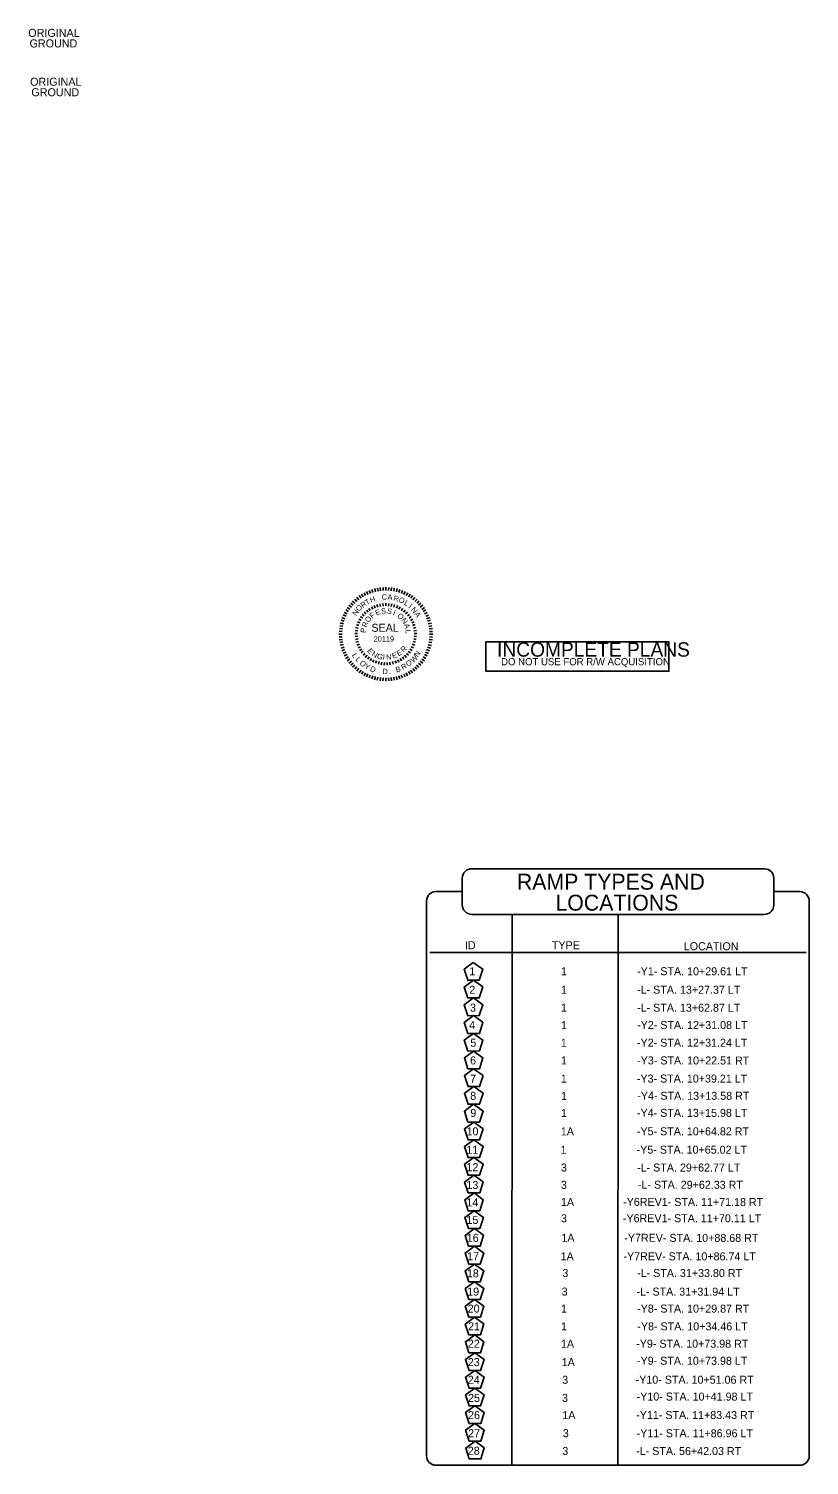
# Model space of a CAD drawing. Extents: x 1725232 to 1728895, y 538685 to 540544.
# Drawn here: x 1728215 to 1728895, y 539219 to 540472 of the extents above; entities that cross this region are included whole.
import ezdxf

# ---------------------------------------------------------------- set-up
doc = ezdxf.new("R2010")
doc.units = 0
for name, color, linetype in [('Default', 7, 'Continuous'), ('DEV BORDER CELL', 7, 'Continuous'), ('Gray Area Fill Shapes', 7, 'Continuous'), ('Prop Dimension Text', 7, 'Continuous'), ('Sheet Sticker Incomplete CELL', 7, 'Continuous'), ('Sheet Title CELL', 7, 'Continuous')]:
    doc.layers.add(name, color=color, linetype=linetype)

msp = doc.modelspace()

# ---------------------------------------------------------------- linework, layer by layer
at = {"layer": 'Default'}
for p, q in [((1728636.1, 539699.3), (1728636, 539218.9)), ((1728728.5, 539699.3), (1728728.4, 539218.9)), ((1728564.4, 539666.2), (1728728.5, 539666.2)), ((1728728.5, 539666.2), (1728892.6, 539666.1))]:
    msp.add_line(p, q, dxfattribs=at)
for points in [[(1728602.3, 539657.4), (1728594.2, 539651.5), (1728597.4, 539642), (1728607.4, 539642), (1728610.5, 539651.6)], [(1728602.4, 539642), (1728594.3, 539636), (1728597.4, 539626.5), (1728607.5, 539626.5), (1728610.5, 539636.1)], [(1728602.4, 539626.5), (1728594.3, 539620.6), (1728597.5, 539611), (1728607.5, 539611.1), (1728610.6, 539620.6)], [(1728602.5, 539611.1), (1728594.4, 539605.1), (1728597.5, 539595.6), (1728607.6, 539595.6), (1728610.6, 539605.2)], [(1728602.5, 539595.6), (1728594.4, 539589.7), (1728597.6, 539580.1), (1728607.6, 539580.2), (1728610.7, 539589.7)], [(1728602.6, 539580.1), (1728594.5, 539574.2), (1728597.6, 539564.7), (1728607.7, 539564.7), (1728610.7, 539574.3)], [(1728602.6, 539564.7), (1728594.5, 539558.8), (1728597.7, 539549.2), (1728607.7, 539549.2), (1728610.8, 539558.8)], [(1728602.7, 539549.2), (1728594.6, 539543.3), (1728597.7, 539533.8), (1728607.8, 539533.8), (1728610.8, 539543.4)], [(1728602.6, 539533.7), (1728594.5, 539527.7), (1728597.6, 539518.2), (1728607.7, 539518.2), (1728610.8, 539527.8)], [(1728602.7, 539518.2), (1728594.6, 539512.3), (1728597.7, 539502.7), (1728607.7, 539502.8), (1728610.8, 539512.3)], [(1728602.7, 539502.8), (1728594.6, 539496.8), (1728597.7, 539487.3), (1728607.8, 539487.3), (1728610.9, 539496.9)], [(1728602.8, 539487.3), (1728594.7, 539481.4), (1728597.8, 539471.8), (1728607.8, 539471.9), (1728610.9, 539481.4)], [(1728602.8, 539471.8), (1728594.7, 539465.9), (1728597.9, 539456.4), (1728607.9, 539456.4), (1728611, 539466)], [(1728602.9, 539456.4), (1728594.8, 539450.5), (1728597.9, 539440.9), (1728607.9, 539440.9), (1728611, 539450.5)], [(1728602.9, 539440.9), (1728594.8, 539435), (1728598, 539425.5), (1728608, 539425.5), (1728611.1, 539435.1)], [(1728603.2, 539425.3), (1728595.1, 539419.4), (1728598.2, 539409.9), (1728608.2, 539409.9), (1728611.3, 539419.5)], [(1728603.2, 539409.9), (1728595.1, 539403.9), (1728598.3, 539394.4), (1728608.3, 539394.4), (1728611.4, 539404)], [(1728603.3, 539394.4), (1728595.2, 539388.5), (1728598.3, 539378.9), (1728608.4, 539379), (1728611.4, 539388.5)], [(1728603.3, 539379), (1728595.2, 539373), (1728598.4, 539363.5), (1728608.4, 539363.5), (1728611.5, 539373.1)], [(1728603.4, 539363.5), (1728595.3, 539357.6), (1728598.4, 539348), (1728608.5, 539348.1), (1728611.5, 539357.6)], [(1728603.4, 539348), (1728595.3, 539342.1), (1728598.5, 539332.6), (1728608.5, 539332.6), (1728611.6, 539342.2)], [(1728603.5, 539332.6), (1728595.4, 539326.7), (1728598.5, 539317.1), (1728608.6, 539317.1), (1728611.6, 539326.7)], [(1728603.5, 539317.1), (1728595.4, 539311.2), (1728598.6, 539301.7), (1728608.6, 539301.7), (1728611.7, 539311.2)], [(1728603.6, 539301.7), (1728595.5, 539295.7), (1728598.6, 539286.2), (1728608.7, 539286.2), (1728611.7, 539295.8)], [(1728603.6, 539286.2), (1728595.5, 539280.3), (1728598.7, 539270.7), (1728608.7, 539270.8), (1728611.8, 539280.3)], [(1728603.7, 539270.8), (1728595.6, 539264.8), (1728598.7, 539255.3), (1728608.8, 539255.3), (1728611.8, 539264.9)], [(1728603.7, 539255.3), (1728595.6, 539249.4), (1728598.8, 539239.8), (1728608.8, 539239.9), (1728611.9, 539249.4)], [(1728603.8, 539239.8), (1728595.7, 539233.9), (1728598.8, 539224.4), (1728608.9, 539224.4), (1728611.9, 539234)]]:
    msp.add_lwpolyline(points, close=True, dxfattribs=at)
at = {"layer": 'DEV BORDER CELL'}
for p, q in [((1728500.8, 539975.9), (1728502.6, 539973.7)), ((1728502.8, 539977.4), (1728504.4, 539975.1)), ((1728504.9, 539978.7), (1728506.3, 539976.3)), ((1728507.1, 539979.9), (1728508.4, 539977.4)), ((1728509.3, 539981), (1728510.4, 539978.4)), ((1728511.6, 539981.9), (1728512.6, 539979.3)), ((1728513.9, 539982.7), (1728514.7, 539980.1)), ((1728516.3, 539983.4), (1728516.9, 539980.7)), ((1728518.7, 539983.9), (1728519.2, 539981.2)), ((1728521.1, 539984.3), (1728521.5, 539981.5)), ((1728523.6, 539984.5), (1728523.8, 539981.7)), ((1728526.1, 539984.6), (1728526.1, 539981.8)), ((1728528.5, 539984.5), (1728528.4, 539981.7)), ((1728531, 539984.3), (1728530.7, 539981.5)), ((1728533.4, 539983.9), (1728532.9, 539981.2)), ((1728535.8, 539983.4), (1728535.2, 539980.7)), ((1728538.2, 539982.7), (1728537.4, 539980)), ((1728540.6, 539981.9), (1728539.6, 539979.3)), ((1728542.8, 539981), (1728541.7, 539978.4)), ((1728545.1, 539979.9), (1728543.8, 539977.4)), ((1728547.2, 539978.7), (1728545.8, 539976.3)), ((1728549.3, 539977.3), (1728547.7, 539975)), ((1728551.3, 539975.8), (1728549.5, 539973.7)), ((1728489.8, 539962.7), (1728492.3, 539961.4)), ((1728491.1, 539964.9), (1728493.4, 539963.4)), ((1728492.4, 539966.9), (1728494.7, 539965.4)), ((1728493.9, 539968.9), (1728496.1, 539967.2)), ((1728495.5, 539970.8), (1728497.5, 539969)), ((1728497.1, 539972.6), (1728499.1, 539970.7)), ((1728498.9, 539974.3), (1728500.8, 539972.2)), ((1728507.2, 539963), (1728508.8, 539961.3)), ((1728509.2, 539964.7), (1728510.6, 539962.9)), ((1728511.3, 539966.2), (1728512.5, 539964.3)), ((1728513.5, 539967.6), (1728514.6, 539965.5)), ((1728515.9, 539968.7), (1728516.8, 539966.5)), ((1728518.3, 539969.5), (1728519, 539967.3)), ((1728520.9, 539970.1), (1728521.3, 539967.9)), ((1728523.4, 539970.5), (1728523.7, 539968.2)), ((1728526, 539970.6), (1728526, 539968.3)), ((1728526, 539968.3), (1728526, 539970.6)), ((1728528.6, 539970.5), (1728528.4, 539968.2)), ((1728531.2, 539970.1), (1728530.8, 539967.8)), ((1728533.7, 539969.5), (1728533.1, 539967.3)), ((1728536.2, 539968.6), (1728535.3, 539966.5)), ((1728538.6, 539967.5), (1728537.5, 539965.5)), ((1728540.8, 539966.2), (1728539.5, 539964.3)), ((1728542.9, 539964.7), (1728541.5, 539962.9)), ((1728544.9, 539963), (1728543.2, 539961.3)), ((1728553.2, 539974.3), (1728551.3, 539972.2)), ((1728555, 539972.6), (1728553, 539970.6)), ((1728556.6, 539970.8), (1728554.6, 539968.9)), ((1728558.2, 539968.9), (1728556, 539967.2)), ((1728559.7, 539966.9), (1728557.4, 539965.3)), ((1728561, 539964.8), (1728558.6, 539963.4)), ((1728485.8, 539951.1), (1728488.6, 539950.6)), ((1728486.3, 539953.5), (1728489, 539952.8)), ((1728487, 539955.9), (1728489.7, 539955.1)), ((1728487.8, 539958.2), (1728490.4, 539957.2)), ((1728488.8, 539960.5), (1728491.3, 539959.4)), ((1728500.4, 539952), (1728502.6, 539951.3)), ((1728501.3, 539954.5), (1728503.5, 539953.5)), ((1728502.5, 539956.8), (1728504.5, 539955.7)), ((1728503.9, 539959), (1728505.8, 539957.7)), ((1728505.4, 539961.1), (1728507.2, 539959.6)), ((1728546.6, 539961), (1728544.9, 539959.6)), ((1728548.2, 539959), (1728546.3, 539957.7)), ((1728549.6, 539956.8), (1728547.6, 539955.6)), ((1728550.7, 539954.4), (1728548.6, 539953.5)), ((1728551.7, 539952), (1728549.4, 539951.3)), ((1728562.2, 539962.7), (1728559.8, 539961.4)), ((1728563.3, 539960.4), (1728560.8, 539959.3)), ((1728564.3, 539958.2), (1728561.6, 539957.2)), ((1728565.1, 539955.8), (1728562.4, 539955)), ((1728565.7, 539953.4), (1728563, 539952.8)), ((1728566.2, 539951), (1728563.5, 539950.5)), ((1728485.1, 539943.7), (1728487.9, 539943.7)), ((1728485.2, 539946.2), (1728488, 539946)), ((1728485.2, 539941.3), (1728488, 539941.4)), ((1728485.4, 539938.8), (1728488.2, 539939.1)), ((1728485.5, 539948.7), (1728488.2, 539948.3)), ((1728499.1, 539944.4), (1728501.4, 539944.3)), ((1728499.2, 539941.8), (1728501.5, 539941.9)), ((1728499.3, 539947), (1728501.6, 539946.7)), ((1728499.5, 539939.2), (1728501.8, 539939.6)), ((1728499.7, 539949.5), (1728502, 539949)), ((1728552.3, 539949.5), (1728550.1, 539949)), ((1728550.3, 539939.6), (1728552.6, 539939.2)), ((1728552.8, 539946.9), (1728550.5, 539946.6)), ((1728553, 539944.3), (1728550.6, 539944.3)), ((1728552.9, 539941.7), (1728550.6, 539941.9)), ((1728566.6, 539948.6), (1728563.8, 539948.3)), ((1728566.6, 539938.7), (1728563.8, 539939.1)), ((1728566.8, 539946.1), (1728564, 539946)), ((1728566.8, 539941.2), (1728564, 539941.4)), ((1728566.9, 539943.7), (1728564.1, 539943.7)), ((1728485.8, 539936.4), (1728488.5, 539936.9)), ((1728486.3, 539934), (1728489, 539934.6)), ((1728487, 539931.6), (1728489.7, 539932.4)), ((1728487.8, 539929.2), (1728490.4, 539930.2)), ((1728488.7, 539927), (1728491.3, 539928.1)), ((1728489.8, 539924.7), (1728492.3, 539926)), ((1728500, 539936.6), (1728502.3, 539937.2)), ((1728500.8, 539934.2), (1728503, 539935)), ((1728501.9, 539931.8), (1728503.9, 539932.8)), ((1728503.1, 539929.5), (1728505.1, 539930.7)), ((1728504.6, 539927.4), (1728506.4, 539928.8)), ((1728506.3, 539925.4), (1728508, 539926.9)), ((1728508.1, 539923.5), (1728509.7, 539925.3)), ((1728543.9, 539923.5), (1728542.3, 539925.3)), ((1728545.7, 539925.3), (1728544, 539926.9)), ((1728547.4, 539927.3), (1728545.6, 539928.7)), ((1728548.9, 539929.5), (1728546.9, 539930.7)), ((1728550.2, 539931.7), (1728548.1, 539932.8)), ((1728551.2, 539934.1), (1728549, 539934.9)), ((1728552, 539936.6), (1728549.8, 539937.2)), ((1728562.2, 539924.7), (1728559.7, 539926)), ((1728563.3, 539926.9), (1728560.7, 539928)), ((1728564.2, 539929.2), (1728561.6, 539930.2)), ((1728565, 539931.5), (1728562.4, 539932.3)), ((1728565.7, 539933.9), (1728563, 539934.5)), ((1728566.2, 539936.3), (1728563.5, 539936.8)), ((1728491, 539922.6), (1728493.4, 539924)), ((1728492.4, 539920.5), (1728494.7, 539922.1)), ((1728493.8, 539918.5), (1728496, 539920.2)), ((1728495.4, 539916.6), (1728497.5, 539918.5)), ((1728497.1, 539914.8), (1728499.1, 539916.8)), ((1728498.9, 539913.1), (1728500.7, 539915.2)), ((1728500.8, 539911.5), (1728502.5, 539913.7)), ((1728510.2, 539921.9), (1728511.5, 539923.8)), ((1728512.3, 539920.5), (1728513.5, 539922.5)), ((1728514.6, 539919.3), (1728515.6, 539921.4)), ((1728517.1, 539918.3), (1728517.8, 539920.5)), ((1728520.1, 539919.8), (1728519.5, 539917.5)), ((1728522.1, 539917), (1728522.4, 539919.3)), ((1728524.7, 539916.8), (1728524.8, 539919.1)), ((1728527.3, 539916.8), (1728527.2, 539919.1)), ((1728529.9, 539917), (1728529.6, 539919.3)), ((1728532.4, 539917.5), (1728531.9, 539919.8)), ((1728534.9, 539918.3), (1728534.2, 539920.5)), ((1728537.4, 539919.3), (1728536.4, 539921.4)), ((1728539.7, 539920.5), (1728538.5, 539922.5)), ((1728541.8, 539921.9), (1728540.5, 539923.8)), ((1728551.2, 539911.5), (1728549.5, 539913.7)), ((1728553.1, 539913.1), (1728551.3, 539915.2)), ((1728554.9, 539914.8), (1728552.9, 539916.7)), ((1728556.6, 539916.6), (1728554.5, 539918.4)), ((1728558.2, 539918.5), (1728556, 539920.2)), ((1728559.6, 539920.4), (1728557.4, 539922)), ((1728561, 539922.5), (1728558.6, 539924)), ((1728502.8, 539910.1), (1728504.4, 539912.4)), ((1728504.8, 539908.7), (1728506.3, 539911.1)), ((1728507, 539907.5), (1728508.3, 539910)), ((1728509.2, 539906.4), (1728510.4, 539909)), ((1728511.5, 539905.5), (1728512.5, 539908.1)), ((1728513.8, 539904.7), (1728514.7, 539907.3)), ((1728516.2, 539904), (1728516.9, 539906.7)), ((1728518.6, 539903.5), (1728519.1, 539906.2)), ((1728521.1, 539903.1), (1728521.4, 539905.9)), ((1728523.5, 539902.9), (1728523.7, 539905.7)), ((1728526, 539902.8), (1728526, 539905.6)), ((1728528.5, 539902.9), (1728528.3, 539905.7)), ((1728530.9, 539903.1), (1728530.6, 539905.9)), ((1728533.4, 539903.5), (1728532.9, 539906.2)), ((1728535.8, 539904), (1728535.1, 539906.7)), ((1728538.1, 539904.7), (1728537.3, 539907.3)), ((1728540.5, 539905.5), (1728539.5, 539908.1)), ((1728542.8, 539906.4), (1728541.6, 539908.9)), ((1728545, 539907.5), (1728543.7, 539910)), ((1728547.1, 539908.7), (1728545.7, 539911.1)), ((1728549.2, 539910), (1728547.6, 539912.3))]:
    msp.add_line(p, q, dxfattribs=at)
at = {"layer": 'Sheet Sticker Incomplete CELL'}
msp.add_lwpolyline([(1728613.3, 539911.4), (1728613.3, 539936.9), (1728772.8, 539936.9), (1728772.8, 539911.4)], close=True, dxfattribs=at)
at = {"layer": 'Sheet Title CELL'}
for p, q in [((1728600.9, 539739.2), (1728856.1, 539739.1)), ((1728592.7, 539707.5), (1728592.7, 539731)), ((1728864.3, 539707.5), (1728864.3, 539730.9)), ((1728569.8, 539719.3), (1728592.7, 539719.3)), ((1728864.3, 539719.2), (1728887, 539719.2)), ((1728561.5, 539227.1), (1728561.6, 539711.1)), ((1728895.1, 539227.1), (1728895.2, 539711)), ((1728600.9, 539699.3), (1728856.1, 539699.3)), ((1728569.7, 539218.9), (1728887, 539218.9))]:
    msp.add_line(p, q, dxfattribs=at)
for centre, start, end in [((1728600.9, 539731), 90, 180), ((1728856.1, 539730.9), 360, 90), ((1728569.8, 539711.1), 90, 180), ((1728887, 539711), 360, 90), ((1728600.9, 539707.5), 180, 270), ((1728856.1, 539707.5), 270, 360), ((1728569.7, 539227.1), 180, 270), ((1728887, 539227.1), 270, 360)]:
    msp.add_arc(centre, 8.18, start, end, dxfattribs=at)

# ---------------------------------------------------------------- texts
at = {"layer": 'Default'}
for s, height, p in [('ID', 6.98, (1728595, 539669)), ('TYPE', 6.98, (1728670.8, 539669)), ('LOCATION', 6.98, (1728785.8, 539668.1)), ('1', 6.98, (1728598.8, 539646.3)), ('1', 6.98, (1728678.7, 539646.3)), ('-Y1- STA. 10+29.61 LT', 6.978, (1728745.1, 539646.3)), ('2', 6.98, (1728598.8, 539630.1)), ('1', 6.98, (1728678.7, 539630.1)), ('-L- STA. 13+27.37 LT', 6.978, (1728745.1, 539630.2)), ('3', 6.98, (1728599.4, 539614.5)), ('1', 6.98, (1728678.7, 539614.5)), ('-L- STA. 13+62.87 LT', 6.978, (1728745.1, 539614.5)), ('4', 6.98, (1728598.7, 539599.3)), ('1', 6.98, (1728678.8, 539599.3)), ('-Y2- STA. 12+31.08 LT', 6.978, (1728745.1, 539599.4)), ('5', 6.98, (1728599.7, 539583.9)), ('1', 6.98, (1728678.6, 539583.9)), ('-Y2- STA. 12+31.24 LT', 6.978, (1728745, 539584)), ('6', 6.98, (1728599.5, 539568.5)), ('1', 6.98, (1728678.7, 539568.5)), ('-Y3- STA. 10+22.51 RT', 6.978, (1728745.1, 539568.5)), ('7', 6.98, (1728599.5, 539552.6)), ('1', 6.98, (1728678.6, 539552.6)), ('-Y3- STA. 10+39.21 LT', 6.978, (1728744.9, 539552.7)), ('8', 6.98, (1728599.6, 539537.6)), ('1', 6.98, (1728678.8, 539537.6)), ('-Y4- STA. 13+13.58 RT', 6.978, (1728745.2, 539537.7)), ('9', 6.98, (1728599.7, 539522.7)), ('1', 6.98, (1728678.7, 539522.7)), ('-Y4- STA. 13+15.98 LT', 6.978, (1728745, 539522.8)), ('10', 6.98, (1728596.4, 539506.6)), ('1A', 6.98, (1728678.6, 539506.6)), ('-Y5- STA. 10+64.82 RT', 6.978, (1728744.9, 539506.7)), ('11', 6.98, (1728596.3, 539490.6)), ('1', 6.98, (1728678.3, 539490.6)), ('-Y5- STA. 10+65.02 LT', 6.978, (1728744.7, 539490.7)), ('12', 6.98, (1728596.3, 539475.4)), ('3', 6.98, (1728678.7, 539475.1)), ('-L- STA. 29+62.77 LT', 6.978, (1728745.1, 539475.1)), ('13', 6.98, (1728596.3, 539459.9)), ('3', 6.98, (1728678.7, 539460)), ('-L- STA. 29+62.33 RT', 6.978, (1728745.8, 539460.1)), ('14', 6.98, (1728596.3, 539444.7)), ('1A', 6.98, (1728678.7, 539445)), ('-Y6REV1- STA. 11+71.18 RT', 6.978, (1728732.9, 539445.1)), ('3', 6.98, (1728678.7, 539430.8)), ('-Y6REV1- STA. 11+70.11 LT', 6.978, (1728732.7, 539430.9)), ('15', 6.98, (1728596.3, 539429.4)), ('16', 6.98, (1728596.6, 539413.8)), ('1A', 6.98, (1728679.1, 539413.8)), ('-Y7REV- STA. 10+88.68 RT', 6.978, (1728733.9, 539413.8)), ('17', 6.98, (1728596.9, 539397.7)), ('1A', 6.98, (1728678.4, 539397.7)), ('-Y7REV- STA. 10+86.74 LT', 6.978, (1728733.2, 539397.7)), ('18', 6.98, (1728596.7, 539382.8)), ('3', 6.98, (1728679.9, 539383.1)), ('-L- STA. 31+33.80 RT', 6.978, (1728745.1, 539383.1)), ('19', 6.98, (1728597, 539366.9)), ('3', 6.98, (1728679.3, 539366.9)), ('-L- STA. 31+31.94 LT', 6.978, (1728744.5, 539366.9)), ('20', 6.98, (1728597.4, 539352.1)), ('1', 6.98, (1728678.8, 539352.1)), ('-Y8- STA. 10+29.87 RT', 6.978, (1728745.1, 539352.1)), ('21', 6.98, (1728597.7, 539336.6)), ('1', 6.98, (1728678.8, 539336.6)), ('-Y8- STA. 10+34.46 LT', 6.978, (1728745.3, 539336.6)), ('22', 6.98, (1728597.5, 539321.4)), ('1A', 6.98, (1728678.7, 539321.4)), ('-Y9- STA. 10+73.98 RT', 6.978, (1728744.3, 539321.5)), ('23', 6.98, (1728597.5, 539305.4)), ('1A', 6.98, (1728679.4, 539305.4)), ('-Y9- STA. 10+73.98 LT', 6.978, (1728745, 539306.6)), ('24', 6.98, (1728597.5, 539290)), ('3', 6.98, (1728679.8, 539290)), ('-Y10- STA. 10+51.06 RT', 6.978, (1728743.8, 539290.1)), ('25', 6.98, (1728597.7, 539274.2)), ('3', 6.98, (1728679.6, 539274.2)), ('-Y10- STA. 10+41.98 LT', 6.978, (1728744.7, 539275.4)), ('26', 6.98, (1728597.7, 539259.2)), ('1A', 6.98, (1728679.9, 539259.2)), ('-Y11- STA. 11+83.43 RT', 6.978, (1728744.3, 539259.3)), ('27', 6.98, (1728597.8, 539243.4)), ('3', 6.98, (1728680.3, 539243.4)), ('-Y11- STA. 11+86.96 LT', 6.978, (1728744.7, 539243.4)), ('28', 6.98, (1728597.5, 539228.1)), ('3', 6.98, (1728679.9, 539227.9)), ('-L- STA. 56+42.03 RT', 6.978, (1728744.3, 539227.9))]:
    msp.add_text(s, height=height, rotation=359.9462, dxfattribs=at).set_placement(p)
at = {"layer": 'DEV BORDER CELL'}
for s, height, rotation, p in [('H', 4.64, 21.0146, (1728513.1, 539971)), ('C', 4.64, 357.3039, (1728522.3, 539973.9)), ('A', 4.64, 357.3039, (1728527.4, 539973.8)), ('R', 4.64, 345.2946, (1728532.3, 539973.1)), ('O', 4.64, 342.2378, (1728536.8, 539971.8)), ('N', 4.64, 53.6237, (1728500.2, 539959.3)), ('O', 4.64, 51.6643, (1728502.9, 539963.2)), ('R', 4.64, 38.6075, (1728506.2, 539966.4)), ('T', 4.64, 30.4466, (1728509.4, 539968.9)), ('F', 4.64, 38.1876, (1728514.1, 539957.1)), ('E', 4.64, 22.8914, (1728517.9, 539959.8)), ('S', 4.64, 7.5951, (1728522.2, 539961.3)), ('S', 4.64, 352.2989, (1728526.8, 539961.7)), ('I', 4.64, 337.0026, (1728531.8, 539960.7)), ('L', 4.64, 329.1015, (1728541.5, 539969.7)), ('I', 4.64, 319.5261, (1728545.3, 539967)), ('N', 4.64, 310.2316, (1728547.6, 539964.9)), ('R', 4.64, 68.7801, (1728509.2, 539949.2)), ('O', 4.64, 53.4838, (1728511, 539953.4)), ('SEAL', 6.97, 359.947, (1728513.5, 539945.8)), ('O', 4.64, 321.7064, (1728535.5, 539958.9)), ('N', 4.64, 306.4101, (1728539.1, 539955.8)), ('A', 4.64, 291.1139, (1728541.6, 539952)), ('A', 4.64, 300.4641, (1728550.7, 539961.4)), ('P', 4.64, 84.0763, (1728508.5, 539944.6)), ('20119', 4.64, 359.947, (1728515.4, 539937.3)), ('L', 4.64, 275.8176, (1728543.1, 539947.4)), ('L', 4.64, 303.882, (1728496.3, 539925.3)), ('E', 4.64, 310.0171, (1728509.4, 539929)), ('N', 4.64, 330.8721, (1728513.3, 539925.1)), ('G', 4.64, 339.6384, (1728517.8, 539922.9)), ('I', 4.64, 357.7332, (1728523.3, 539921.4)), ('N', 4.64, 5.3628, (1728526.5, 539921.3)), ('E', 4.64, 20.7549, (1728532.4, 539922.3)), ('E', 4.64, 30.7408, (1728537.1, 539924.3)), ('R', 4.64, 44.5119, (1728541.5, 539927.5)), ('W', 4.64, 43.2714, (1728549.9, 539918.6)), ('N', 4.64, 52.154, (1728553.8, 539923.3)), ('L', 4.64, 311.9538, (1728499.2, 539921.4)), ('O', 4.64, 320.5966, (1728502.7, 539917.7)), ('Y', 4.64, 329.2691, (1728506.9, 539914.5)), ('D', 4.64, 338.2416, (1728511.8, 539911.8)), ('D', 4.64, 356.0369, (1728523, 539909)), ('B', 4.64, 16.5636, (1728535.3, 539910.3)), ('R', 4.64, 25.5662, (1728540.7, 539912.4)), ('O', 4.64, 34.3888, (1728545.3, 539915.2)), ('.', 4.64, 3.7793, (1728528.9, 539909))]:
    msp.add_text(s, height=height, rotation=rotation, dxfattribs=at).set_placement(p)
at = {"layer": 'Gray Area Fill Shapes'}
for s, height, p in [('RAMP TYPES AND', 13.866, (1728640.3, 539720.9)), ('LOCATIONS', 13.87, (1728673.9, 539702.6))]:
    msp.add_text(s, height=height, rotation=360, dxfattribs=at).set_placement(p)
at = {"layer": 'Prop Dimension Text'}
for s, p in [('ORIGINAL', (1728214.3, 540464.6)), ('GROUND', (1728215.4, 540455.4)), ('ORIGINAL', (1728215.9, 540422)), ('GROUND', (1728217, 540412.8))]:
    msp.add_text(s, height=7.01, dxfattribs=at).set_placement(p)
at = {"layer": 'Sheet Sticker Incomplete CELL'}
for s, height, p in [('INCOMPLETE PLANS', 12.499, (1728623, 539924.1)), ('DO NOT USE FOR R/W ACQUISITION', 6.249, (1728626.5, 539916.6))]:
    msp.add_text(s, height=height, dxfattribs=at).set_placement(p)

doc.saveas('drawing.dxf')
